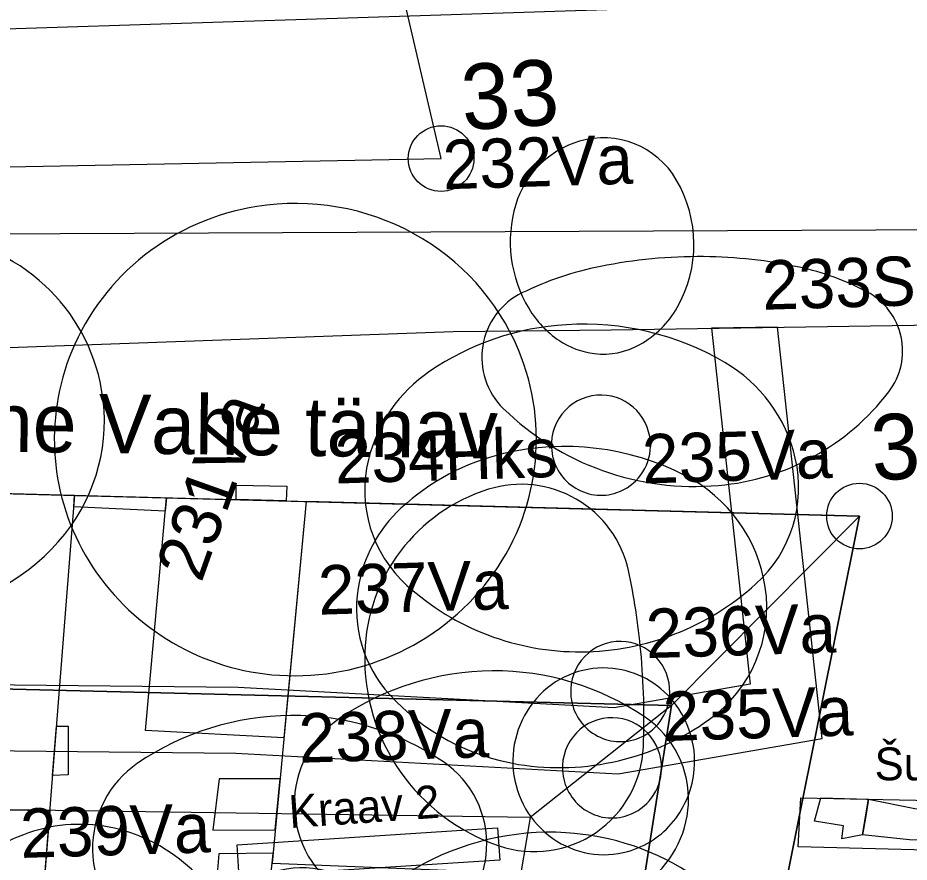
# Model space of a CAD drawing. Extents: x 738423 to 738903, y 6589762 to 6590172.
# Drawn here: x 738678 to 738705.18, y 6589928.62 to 6589954.37 of the extents above; entities that cross this region are included whole.
import ezdxf

# ---------------------------------------------------------------- set-up
doc = ezdxf.new("R2010")
doc.units = 0
for name, color, linetype in [('_1927_hoonestus', 7, 'Continuous'), ('_1927_katuse_kalded', 7, 'Continuous'), ('_1927_koordin_punktid_nr', 7, 'Continuous'), ('_1927_krundi_piir', 7, 'Continuous'), ('_1927_uhepoolne_katusekalle', 7, 'Continuous'), ('_ajalooline_liivavall_linnamuur', 7, 'Continuous'), ('_arheol_Raamatukogu_tekst', 7, 'Continuous'), ('_arheol_Rüütli8_tekst', 7, 'Continuous'), ('_arheol_Rüütli8_tranžee', 7, 'Continuous'), ('_arheol_Suur10c_müür', 7, 'Continuous'), ('_arheol_Suur10c_sõidutee', 7, 'Continuous'), ('_arheol_Suur10c_tranžee', 7, 'Continuous'), ('a_dendro_II_Vkl_puu', 7, 'Continuous'), ('a_dendro_III_vk_puu', 7, 'Continuous'), ('a_dendro_puu_nr', 7, 'Continuous'), ('a_dendro_V_vk_puu', 7, 'Continuous'), ('Default', 7, 'Continuous'), ('plan_ala', 7, 'Continuous'), ('v_olol_kitsendus_tehnov', 7, 'Continuous'), ('v_vormistus_tekst', 7, 'Continuous')]:
    doc.layers.add(name, color=color, linetype=linetype)

# ---------------------------------------------------------------- blocks, each defined once
blk = doc.blocks.new('_U678')
at = {"layer": 'Default'}
for centre, radius, start, end in [((-0.002579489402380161, 0.001985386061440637), 0.01111431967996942, 82.0551215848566, 139.83879613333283), ((-0.002626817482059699, 0.001646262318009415), 0.011456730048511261, 39.469554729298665, 82.05512158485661), ((-0.0014216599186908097, 0.0010082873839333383), 0.012629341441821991, 139.83879613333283, 193.7438684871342), ((-0.0036379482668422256, 0.0008136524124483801), 0.012766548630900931, 359.2278417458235, 39.46955472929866), ((-0.003454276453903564, 0.0008111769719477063), 0.012582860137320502, 323.95832458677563, 359.2278417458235), ((-0.0016596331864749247, 0.0009500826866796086), 0.012384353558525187, 193.74386848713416, 238.8156217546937), ((-0.0024338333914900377, 6.864704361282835e-05), 0.01132085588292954, 286.7065177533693, 323.95832458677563), ((-0.002354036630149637, -0.00019721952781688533), 0.011043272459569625, 238.81562175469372, 286.7065177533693)]:
    blk.add_arc(centre, radius, start, end, dxfattribs=at)
blk = doc.blocks.new('_U679')
at = {"layer": 'Default'}
for centre, radius, start, end in [((-0.005303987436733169, -0.002190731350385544), 0.01409202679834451, 71.82357012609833, 126.01573997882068), ((-0.005395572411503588, -0.0024696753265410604), 0.014385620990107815, 42.31070554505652, 71.82357012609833), ((-0.004905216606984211, -0.002739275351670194), 0.01477019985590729, 126.01573997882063, 178.85019053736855), ((-0.0057995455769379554, -0.002837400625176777), 0.014931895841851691, 13.354748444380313, 42.31070554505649), ((-0.005892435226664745, -0.002859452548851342), 0.015027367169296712, 335.5989084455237, 13.354748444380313), ((-0.0047907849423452, -0.002741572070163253), 0.014884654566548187, 178.85019053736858, 237.08728458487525), ((-0.005350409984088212, -0.0031053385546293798), 0.014432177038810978, 297.0422816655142, 335.5989084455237), ((-0.005207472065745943, -0.00338535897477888), 0.014117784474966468, 237.08728458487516, 297.0422816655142)]:
    blk.add_arc(centre, radius, start, end, dxfattribs=at)
blk = doc.blocks.new('_U680')
at = {"layer": 'Default'}
for centre, radius, start, end in [((0.0042888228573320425, -0.003380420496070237), 0.007871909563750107, 77.52508910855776, 125.58701075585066), ((0.004748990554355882, -0.0013004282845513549), 0.0057416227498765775, 20.5680724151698, 77.52508910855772), ((0.003367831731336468, -0.0020933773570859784), 0.006289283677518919, 125.58701075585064, 149.88923738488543), ((0.002104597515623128, -0.0013607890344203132), 0.004828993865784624, 149.88923738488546, 177.68803525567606), ((0.005284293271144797, -0.001099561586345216), 0.00516987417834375, 304.7502772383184, 20.568072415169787), ((0.0018743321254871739, -0.0013514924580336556), 0.0045985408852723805, 177.68803525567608, 213.4084481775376), ((0.0030081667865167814, -0.0006036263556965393), 0.005956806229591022, 213.4084481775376, 244.67394466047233), ((0.0037916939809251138, 0.0010519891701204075), 0.00778846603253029, 244.67394466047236, 304.7502772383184)]:
    blk.add_arc(centre, radius, start, end, dxfattribs=at)
blk = doc.blocks.new('_U681')
at = {"layer": 'Default'}
for centre, radius, start, end in [((-0.004661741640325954, 0.008793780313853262), 0.004366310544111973, 30.329947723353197, 139.92832471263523), ((0.004756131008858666, 0.0008711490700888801), 0.016673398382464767, 139.92832471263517, 189.36497032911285), ((-0.017946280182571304, 0.001021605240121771), 0.019757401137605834, 15.608346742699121, 30.329947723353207), ((-0.028499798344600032, -0.0019266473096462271), 0.03071499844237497, 3.812839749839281, 15.608346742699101), ((-0.026823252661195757, -0.0018149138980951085), 0.029034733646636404, 352.17634135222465, 3.8128397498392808), ((0.002824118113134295, 0.0005525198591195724), 0.014715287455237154, 189.36497032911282, 236.85170049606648), ((-0.01392376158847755, -0.0035873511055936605), 0.01601404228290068, 336.48565132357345, 352.17634135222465), ((-0.0029873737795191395, -0.008345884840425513), 0.004087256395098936, 236.85170049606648, 336.48565132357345)]:
    blk.add_arc(centre, radius, start, end, dxfattribs=at)
blk = doc.blocks.new('_U682')
at = {"layer": 'Default'}
for centre, radius, start, end in [((-0.0022753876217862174, 0.004291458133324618), 0.007814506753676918, 80.3701075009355, 142.21769029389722), ((-0.002500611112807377, 0.002964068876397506), 0.00916086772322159, 38.521789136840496, 80.3701075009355), ((0.003974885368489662, -0.0005536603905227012), 0.015722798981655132, 142.2176902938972, 184.7001068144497), ((-0.008333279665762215, -0.0016790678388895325), 0.01661598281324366, 7.766989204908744, 38.52178913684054), ((-0.008822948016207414, -0.0017458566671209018), 0.017110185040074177, 334.0583027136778, 7.766989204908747), ((0.004278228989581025, -0.0005287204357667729), 0.016027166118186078, 184.70010681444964, 226.45663741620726), ((-0.001672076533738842, -0.005224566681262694), 0.009158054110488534, 287.3630912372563, 334.0583027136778), ((-0.0013038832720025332, -0.006402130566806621), 0.007924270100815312, 226.45663741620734, 287.3630912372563)]:
    blk.add_arc(centre, radius, start, end, dxfattribs=at)
blk = doc.blocks.new('_U685')
at = {"layer": 'Default'}
for centre, radius, start, end in [((-0.0013909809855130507, 0.0010517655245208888), 0.00778143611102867, 85.11093491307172, 136.67778974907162), ((-0.0014517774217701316, 0.0003410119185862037), 0.008494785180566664, 47.07579184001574, 85.11093491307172), ((-0.005171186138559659, -0.003658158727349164), 0.013956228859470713, 17.620287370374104, 47.07579184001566), ((0.002810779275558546, -0.002910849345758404), 0.013556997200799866, 136.67778974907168, 175.15950142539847), ((-0.0072552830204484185, -0.004320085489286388), 0.01614291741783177, 337.28207683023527, 17.620287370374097), ((0.00493323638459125, -0.0030905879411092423), 0.015687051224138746, 175.15950142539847, 219.99965898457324), ((-0.0008345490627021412, -0.007008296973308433), 0.009182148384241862, 282.8730022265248, 337.28207683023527), ((-0.0006577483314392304, -0.007781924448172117), 0.008388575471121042, 219.99965898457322, 282.8730022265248)]:
    blk.add_arc(centre, radius, start, end, dxfattribs=at)
blk = doc.blocks.new('_U690')
at = {"layer": 'Default'}
for centre, radius, start, end in [((-0.003374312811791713, 0.004949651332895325), 0.00931776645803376, 75.98881493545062, 141.81307745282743), ((-0.0037682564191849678, 0.003370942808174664), 0.010944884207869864, 34.56599987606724, 75.98881493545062), ((0.0014665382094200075, 0.0011420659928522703), 0.01547662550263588, 141.8130774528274, 191.68419382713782), ((-0.008227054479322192, 0.0002989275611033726), 0.016359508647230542, 0.9371401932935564, 34.56599987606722), ((-0.007523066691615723, 0.00031044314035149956), 0.01565542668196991, 330.06495980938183, 0.9371401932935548), ((0.0005393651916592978, 0.0009503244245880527), 0.014529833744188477, 191.6841938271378, 235.6485071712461), ((-0.0030046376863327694, -0.002291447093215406), 0.01044140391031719, 292.02320364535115, 330.06495980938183), ((-0.002510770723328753, -0.003512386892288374), 0.00912436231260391, 235.6485071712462, 292.02320364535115)]:
    blk.add_arc(centre, radius, start, end, dxfattribs=at)
blk = doc.blocks.new('_U686')
at = {"layer": 'Default'}
for centre, radius, start, end in [((-0.0003832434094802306, 0.0056645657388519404), 0.006358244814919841, 95.27822777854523, 153.5383418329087), ((-0.00039005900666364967, 0.00573834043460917), 0.006284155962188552, 38.521789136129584, 95.27822777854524), ((-0.0086367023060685, -0.0008264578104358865), 0.016824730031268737, 4.749066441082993, 38.5217891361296), ((0.009291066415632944, 0.000849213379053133), 0.017164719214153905, 153.53834183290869, 188.00637392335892), ((-0.008165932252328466, -0.0007873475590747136), 0.016352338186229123, 330.06495980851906, 4.7490664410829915), ((0.00846837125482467, 0.0007334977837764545), 0.016333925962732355, 188.00637392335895, 219.56435589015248), ((0.0007720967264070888, -0.005934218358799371), 0.006038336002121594, 271.3152895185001, 330.06495980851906), ((0.0007651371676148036, -0.005631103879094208), 0.006341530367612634, 219.56435589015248, 271.3152895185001)]:
    blk.add_arc(centre, radius, start, end, dxfattribs=at)
blk = doc.blocks.new('_U687')
at = {"layer": 'Default'}
for centre, radius, start, end in [((-0.00037116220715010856, -0.013056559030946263), 0.020067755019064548, 90.63222332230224, 122.78378534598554), ((-0.00039611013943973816, -0.010795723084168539), 0.017806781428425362, 62.49553610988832, 90.63222332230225), ((0.004559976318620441, -0.0012769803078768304), 0.007075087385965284, 17.12942078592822, 62.49553610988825), ((-0.007146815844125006, -0.0025362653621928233), 0.00755431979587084, 122.78378534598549, 176.44105376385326), ((0.00557950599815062, -0.0009627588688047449), 0.006008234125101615, 315.5978339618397, 17.129420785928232), ((-0.008276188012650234, -0.002466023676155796), 0.006422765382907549, 176.44105376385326, 242.8863827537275), ((-0.0021885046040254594, 0.006644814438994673), 0.016881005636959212, 280.06075412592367, 315.59783396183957), ((-0.0025546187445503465, 0.008708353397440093), 0.01897677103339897, 242.8863827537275, 280.0607541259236)]:
    blk.add_arc(centre, radius, start, end, dxfattribs=at)
blk = doc.blocks.new('_U688')
at = {"layer": 'Default'}
for centre, radius, start, end in [((0.002276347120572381, 0.001824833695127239), 0.011651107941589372, 49.162226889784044, 106.55395243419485), ((0.0021298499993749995, 0.002317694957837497), 0.011136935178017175, 106.55395243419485, 155.37187784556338), ((0.0035985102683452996, 0.0033545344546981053), 0.009629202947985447, 345.3983052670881, 49.162226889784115), ((0.0006497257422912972, 0.002996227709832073), 0.009508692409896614, 155.37187784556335, 208.50422751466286), ((0.0028839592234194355, 0.00354068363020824), 0.010367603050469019, 302.57956319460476, 345.3983052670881), ((0.001212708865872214, 0.003301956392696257), 0.010149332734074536, 208.50422751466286, 236.55502715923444), ((0.001969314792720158, 0.0044474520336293), 0.011522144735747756, 236.5550271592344, 262.8497923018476), ((0.0020243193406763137, 0.0048859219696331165), 0.011964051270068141, 262.84979230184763, 302.5795631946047)]:
    blk.add_arc(centre, radius, start, end, dxfattribs=at)
blk = doc.blocks.new('_U651')
at = {"layer": 'Default'}
for centre, radius, start, end in [((0.0004710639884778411, 0.0003351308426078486), 0.005763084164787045, 99.87682055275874, 149.09162522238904), ((0.00047664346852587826, 0.0003030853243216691), 0.005795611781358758, 49.93101198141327, 99.87682055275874), ((0.0007179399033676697, 0.0005899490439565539), 0.00542075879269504, 358.1639607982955, 49.93101198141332), ((0.00016307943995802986, 0.0005195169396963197), 0.005404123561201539, 149.09162522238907, 200.02741080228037), ((0.000649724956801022, 0.0005921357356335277), 0.005489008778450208, 313.2341935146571, 358.1639607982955), ((0.0002363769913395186, 0.000546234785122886), 0.005482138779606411, 200.02741080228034, 235.3717727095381), ((0.0004126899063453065, 0.0008442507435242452), 0.005835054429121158, 269.72730137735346, 313.23419351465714), ((0.00041248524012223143, 0.0008012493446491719), 0.005792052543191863, 235.37177270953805, 269.72730137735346)]:
    blk.add_arc(centre, radius, start, end, dxfattribs=at)
blk = doc.blocks.new('_U684')
at = {"layer": 'Default'}
for centre, radius, start, end in [((-0.0007021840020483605, 0.003926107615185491), 0.012071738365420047, 92.68935288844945, 165.6556181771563), ((-0.0007637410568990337, 0.0052365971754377), 0.010759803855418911, 21.626253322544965, 92.68935288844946), ((0.003018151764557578, 0.006735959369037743), 0.006691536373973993, 286.6845392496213, 21.62625332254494), ((-0.005943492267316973, 0.005266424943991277), 0.00666176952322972, 165.65561817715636, 271.99147164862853), ((-0.006066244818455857, 0.037045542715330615), 0.03833323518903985, 283.04962547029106, 286.6845392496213), ((-0.007079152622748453, 0.041415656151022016), 0.04281919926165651, 279.61044515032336, 283.049625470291), ((-0.007283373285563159, 0.04262174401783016), 0.0440424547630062, 275.81433712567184, 279.61044515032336), ((-0.007221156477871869, 0.042010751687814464), 0.04342830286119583, 271.99147164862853, 275.81433712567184)]:
    blk.add_arc(centre, radius, start, end, dxfattribs=at)
blk = doc.blocks.new('_U683')
at = {"layer": 'Default'}
for centre, radius, start, end in [((0.00010175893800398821, -2.9195723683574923e-05), 0.0030757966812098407, 97.35783497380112, 149.88923738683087), ((0.00010187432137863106, -3.008927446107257e-05), 0.0030766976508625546, 50.52505290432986, 97.35783497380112), ((0.00015430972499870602, 3.357665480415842e-05), 0.0029942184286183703, 3.012518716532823, 50.52505290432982), ((2.8773528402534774e-05, 1.3130757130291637e-05), 0.002991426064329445, 149.88923738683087, 203.21391915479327), ((0.00014157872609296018, 3.2906662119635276e-05), 0.0030069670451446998, 317.60715168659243, 3.012518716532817), ((4.603189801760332e-05, 2.05326671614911e-05), 0.00301020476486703, 203.21391915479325, 238.22626086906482), ((8.24496394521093e-05, 8.688540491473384e-05), 0.0030870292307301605, 272.8268339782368, 317.60715168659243), ((8.27952253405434e-05, 7.988657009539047e-05), 0.0030800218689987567, 238.2262608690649, 272.8268339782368)]:
    blk.add_arc(centre, radius, start, end, dxfattribs=at)

msp = doc.modelspace()

# ---------------------------------------------------------------- linework, layer by layer
at = {"layer": '_1927_hoonestus'}
for points in [[(738670.9087498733, 6589940.043011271), (738679.7282311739, 6589939.8095354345), (738678.0506429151, 6589918.541122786), (738669.2749026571, 6589918.640213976), (738669.5947892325, 6589922.838186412)], [(738684.6600039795, 6589939.678977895), (738684.6600039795, 6589940.1149650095), (738686.1962693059, 6589940.09199296), (738686.1808616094, 6589939.638716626)], [(738679.7282311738, 6589939.8095354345), (738682.5283834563, 6589939.735407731), (738682.4916710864, 6589939.328665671), (738679.7006569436, 6589939.459950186)], [(738686.7916245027, 6589939.622548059), (738686.1128576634, 6589932.419491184), (738681.8873825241, 6589932.633658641), (738682.5283834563, 6589939.735407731)], [(738703.6658553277, 6589939.175840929), (738686.7916245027, 6589939.622548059), (738685.7524954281, 6589928.595336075), (738691.0609477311, 6589928.3767996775), (738689.9894215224, 6589918.406316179), (738699.2597677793, 6589917.239834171)], [(738679.1733217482, 6589932.774410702), (738679.5312519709, 6589932.774410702), (738679.5312519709, 6589931.290547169), (738679.0544191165, 6589931.266966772)], [(738685.9941946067, 6589931.160241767), (738684.1324107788, 6589931.160241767), (738683.9471745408, 6589929.596808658), (738685.8485556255, 6589929.614724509)], [(738683.7945797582, 6589924.85083232), (738685.3485059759, 6589924.85083232), (738685.7524954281, 6589928.595336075), (738685.7811858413, 6589928.899798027), (738684.1245318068, 6589928.878209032)]]:
    msp.add_lwpolyline(points, close=True, dxfattribs=at)
at = {"layer": '_1927_katuse_kalded'}
for points in [[(738703.6658553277, 6589939.175840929), (738697.9292015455, 6589933.403840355), (738670.4536419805, 6589934.083874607), (738670.9086865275, 6589940.042181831)], [(738703.6658553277, 6589939.175840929), (738697.9292015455, 6589933.403840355), (738695.4504945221, 6589917.7191527), (738699.2597677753, 6589917.239834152)], [(738697.9292015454, 6589933.403840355), (738693.6272828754, 6589929.981278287), (738670.1667035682, 6589930.326732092), (738670.4536419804, 6589934.083874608)], [(738693.6272828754, 6589929.981278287), (738691.6412212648, 6589918.198471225), (738695.4504945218, 6589917.719152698), (738697.9292015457, 6589933.403840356)]]:
    msp.add_lwpolyline(points, close=True, dxfattribs=at)
at = {"layer": '_1927_koordin_punktid_nr'}
for centre in [(738690.9043289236, 6589950.074278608), (738703.6658553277, 6589939.175840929)]:
    msp.add_circle(centre, 0.9999999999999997, dxfattribs=at)
at = {"layer": '_1927_krundi_piir'}
msp.add_lwpolyline([(738649.2135835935, 6589949.273370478), (738690.9043289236, 6589950.074278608), (738685.5858837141, 6589972.9080395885), (738646.6848373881, 6589968.012491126)], close=True, dxfattribs=at)
msp.add_lwpolyline([(738642.9591139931, 6589940.778512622), (738670.908755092, 6589940.043011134), (738703.6658553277, 6589939.175840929), (738699.2597677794, 6589917.23983417), (738689.9894215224, 6589918.406316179), (738669.274902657, 6589918.640213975), (738669.45830989, 6589921.006172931), (738669.5947892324, 6589922.838186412), (738670.908755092, 6589940.043011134)], dxfattribs=at)
at = {"layer": '_1927_uhepoolne_katusekalle'}
msp.add_lwpolyline([(738670.1667035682, 6589930.326732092), (738678.9700315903, 6589930.197104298), (738678.0506429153, 6589918.541122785), (738669.2749026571, 6589918.640213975)], close=True, dxfattribs=at)
at = {"layer": '_ajalooline_liivavall_linnamuur'}
msp.add_lwpolyline([(738708.289405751, 6589968.14747116), (738780.2257645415, 6589985.561122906), (738769.667506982, 6589952.525563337), (738767.8196994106, 6589945.734830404), (738713.208654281, 6589947.930212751), (738615.9368314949, 6589947.498858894), (738617.4577657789, 6589962.743100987), (738623.554579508, 6589962.319832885), (738622.8971321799, 6589952.276700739), (738711.4568073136, 6589955.13)], close=True, dxfattribs=at)
at = {"layer": '_arheol_Rüütli8_tranžee'}
msp.add_lwpolyline([(738684.6874199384, 6589929.1563526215), (738692.6296929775, 6589929.666277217), (738692.6925779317, 6589928.686819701), (738684.7503048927, 6589928.176895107)], close=True, dxfattribs=at)
at = {"layer": '_arheol_Suur10c_müür'}
msp.add_line((738703.7579999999, 6589929.457), (738703.862, 6589930.040999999), dxfattribs=at)
msp.add_lwpolyline([(738702.292, 6589929.870999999), (738702.4856666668, 6589930.588999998), (738703.9416705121, 6589930.547408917), (738703.862, 6589930.040999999), (738703.7579999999, 6589929.457), (738703.1329999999, 6589929.34), (738703.176, 6589929.73)], close=True, dxfattribs=at)
msp.add_lwpolyline([(738703.1329999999, 6589929.34), (738703.176, 6589929.73), (738702.292, 6589929.870999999)], dxfattribs=at)
at = {"layer": '_arheol_Suur10c_sõidutee'}
msp.add_lwpolyline([(738703.9416705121, 6589930.547408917), (738705.357, 6589930.26), (738707.458, 6589930.171999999), (738708.5889999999, 6589930.277999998), (738708.472, 6589929.209), (738707.887, 6589929.296), (738705.1919999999, 6589929.309999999), (738703.758, 6589929.457)], close=True, dxfattribs=at)
at = {"layer": '_arheol_Suur10c_tranžee'}
msp.add_lwpolyline([(738701.794, 6589929.093999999), (738701.879, 6589930.589), (738711.897, 6589930.387), (738711.607, 6589928.834)], close=True, dxfattribs=at)
at = {"layer": 'plan_ala'}
msp.add_lwpolyline([(738772.2221966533, 6589837.873120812), (738583.11, 6589865.669999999), (738583.11, 6589865.669999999), (738577.13, 6589865.85), (738565.7035831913, 6589866.139410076), (738565.4500000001, 6589885.77), (738564.4932191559, 6589941.052825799), (738581.9, 6589941.1499999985), (738615.11, 6589942.169999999), (738650.0499999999, 6589943.319999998), (738691.2690631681, 6589944.800325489), (738696.0901513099, 6589944.851371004), (738713.89, 6589945.129999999), (738703.51, 6589987.789999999), (738752.8799999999, 6590000.39), (738783.1408503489, 6590007.463828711), (738767.5688789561, 6589951.87996157)], close=True, dxfattribs=at)
at = {"layer": 'v_olol_kitsendus_tehnov'}
msp.add_lwpolyline([(738657.5236514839, 6589931.178043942), (738674.0238867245, 6589932.064447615), (738684.6483694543, 6589931.951173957), (738696.3015328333, 6589931.3201832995), (738702.5245470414, 6589932.39569243), (738701.1625300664, 6589944.936942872), (738699.154078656, 6589944.9064775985), (738700.3334863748, 6589934.046666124), (738696.1838115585, 6589933.329487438), (738684.713129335, 6589933.950597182), (738673.980859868, 6589934.065020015), (738656.984348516, 6589933.151956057)], dxfattribs=at)

# ---------------------------------------------------------------- block references
at = {"layer": 'a_dendro_II_Vkl_puu', "xscale": 500.0000000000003, "yscale": 500.0000000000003, "rotation": 85.69234851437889}
for name, p in [('_U678', (738675.105, 6589943.26)), ('_U686', (738686.292, 6589929.021000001))]:
    msp.add_blockref(name, p, dxfattribs=at)
at = {"layer": 'a_dendro_III_vk_puu', "xscale": 500.0000000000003, "yscale": 500.0000000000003, "rotation": 85.69234851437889}
for name, p in [('_U679', (738685.2615000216, 6589944.241)), ('_U681', (738698.89, 6589946.011)), ('_U682', (738694.707, 6589940.937000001)), ('_U685', (738692.7899999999, 6589937.006999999)), ('_U684', (738696.5948477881, 6589935.0421827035)), ('_U686', (738692.4450000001, 6589930.383000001)), ('_U651', (738696.125, 6589931.454)), ('_U688', (738681.4149999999, 6589923.042999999)), ('_U690', (738694.6830000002, 6589925.447)), ('_U687', (738685.9634679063, 6589922.699999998))]:
    msp.add_blockref(name, p, dxfattribs=at)
at = {"layer": 'a_dendro_V_vk_puu', "xscale": 500.0000000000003, "yscale": 500.0000000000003, "rotation": 85.69234851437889}
for name, p in [('_U680', (738695.1046848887, 6589945.529456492)), ('_U683', (738695.7880000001, 6589941.291999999)), ('_U683', (738696.376466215, 6589933.779160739)), ('_U683', (738696.125, 6589931.454))]:
    msp.add_blockref(name, p, dxfattribs=at)

# ---------------------------------------------------------------- texts
at = {"layer": '_1927_koordin_punktid_nr'}
for s, p in [('33', (738691.5780901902, 6589950.939035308)), ('3', (738704.075084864, 6589940.249981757))]:
    msp.add_text(s, height=1.9999999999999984, rotation=3.560863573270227, dxfattribs=at).set_placement(p)
at = {"layer": '_arheol_Raamatukogu_tekst'}
msp.add_text('Šurf 3', height=1.0000000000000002, rotation=359.99285992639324, dxfattribs=at).set_placement((738704.1253877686, 6589931.121001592))
at = {"layer": '_arheol_Rüütli8_tekst'}
msp.add_text('Kraav 2', height=1.0000000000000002, rotation=4.002836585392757, dxfattribs=at).set_placement((738686.293774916, 6589929.661024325))
at = {"layer": 'a_dendro_puu_nr'}
for s, height, rotation, p in [('232Va', 1.5, 1.7381147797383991, (738690.9766066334, 6589949.138164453)), ('233Sa', 1.5, 1.7381147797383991, (738700.7165191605, 6589945.464279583)), ('231Va', 1.4999999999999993, 70.36105075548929, (738683.5916003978, 6589937.118088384)), ('234Hks', 1.5, 1.7381147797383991, (738687.6825259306, 6589940.1671036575)), ('235Va', 1.5, 1.7381147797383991, (738697.0574179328, 6589940.1671036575)), ('237Va', 1.5, 1.7381147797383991, (738687.1758935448, 6589936.168241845)), ('236Va', 1.5, 1.7381147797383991, (738697.1690257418, 6589934.843906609)), ('235Va', 1.5, 1.7381147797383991, (738697.6928701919, 6589932.316133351)), ('235Va', 1.5, 1.7381147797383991, (738697.6928701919, 6589932.316133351)), ('238Va', 1.5, 1.7381147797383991, (738686.5820313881, 6589931.654055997)), ('239Va', 1.5, 1.7381147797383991, (738678.0898159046, 6589928.751467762))]:
    msp.add_text(s, height=height, rotation=rotation, dxfattribs=at).set_placement(p)
at = {"layer": 'v_vormistus_tekst'}
msp.add_text('ajalooline Vahe tänav', height=1.7999999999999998, rotation=359.20505069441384, dxfattribs=at).set_placement((738669.6088702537, 6589941.249649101))

doc.saveas('drawing.dxf')
